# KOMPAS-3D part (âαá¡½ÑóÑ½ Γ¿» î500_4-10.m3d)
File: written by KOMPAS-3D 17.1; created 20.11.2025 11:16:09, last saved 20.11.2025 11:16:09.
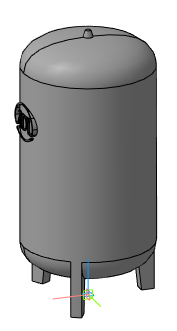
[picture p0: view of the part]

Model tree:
1. Операция без истории:3

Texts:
  REVIT MATERIAL OVERRIDDEN
  REVIT MATERIAL ID
  REVIT SUBCATEGORY ID
  REVIT CATEGORY ID
  REVIT ELEMENT ID
  REVIT BREP TAG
